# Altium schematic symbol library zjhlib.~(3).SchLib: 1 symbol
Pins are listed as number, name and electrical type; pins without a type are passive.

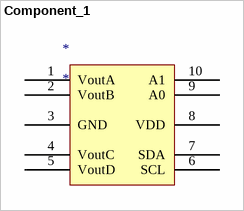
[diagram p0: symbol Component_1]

## Component_1
designator *
pins: 1 VoutA, 2 VoutB, 3 GND, 4 VoutC, 5 VoutD, 6 SCL, 7 SDA, 8 VDD, 9 A0, 10 A1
